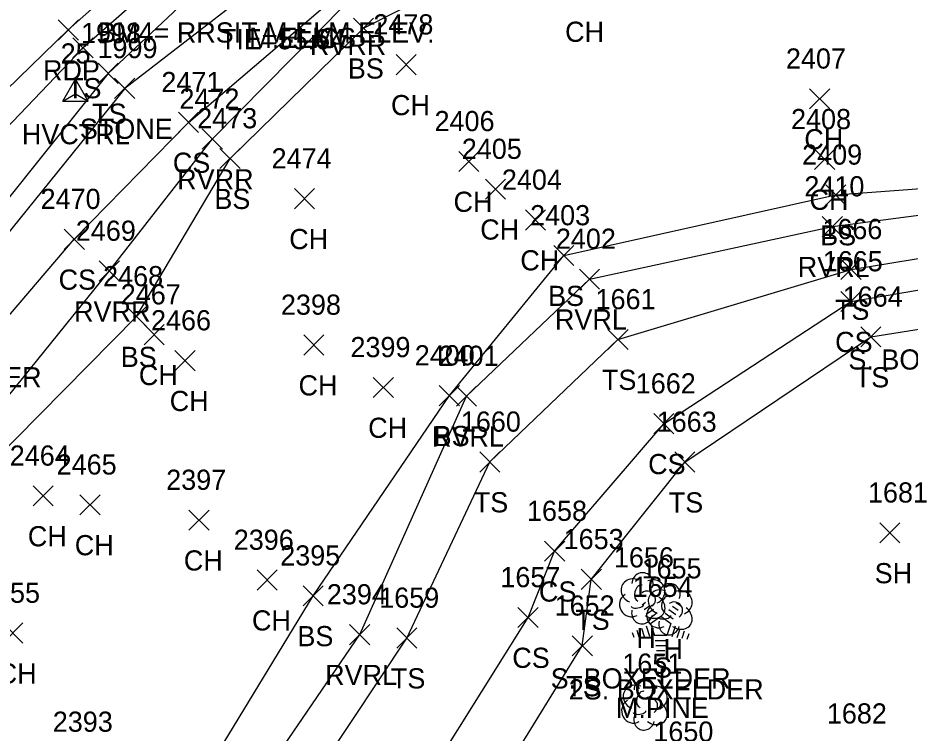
# Model space of a CAD drawing. Extents: x 1459992 to 1461532, y 647785 to 648535.
# Drawn here: x 1461337.5 to 1461426, y 648285.6 to 648356.5 of the extents above; entities that cross this region are included whole.
import ezdxf

# ---------------------------------------------------------------- set-up
doc = ezdxf.new("R2010")
doc.units = 0
for name, color, linetype in [('C_A', 7, 'Continuous'), ('C_C', 7, 'Continuous'), ('C_I', 7, 'Continuous'), ('CPSM', 7, 'Continuous'), ('L_A', 7, 'Continuous'), ('L_C', 7, 'Continuous'), ('L_I', 7, 'Continuous'), ('L_TIC', 7, 'Continuous'), ('LASF', 7, 'Continuous'), ('LAWE', 7, 'Continuous'), ('LELB', 7, 'Continuous'), ('LTC', 7, 'Continuous'), ('LTD', 7, 'Continuous'), ('P_A', 7, 'Continuous'), ('P_TIC', 7, 'Continuous'), ('PET', 7, 'Continuous')]:
    doc.layers.add(name, color=color, linetype=linetype)

msp = doc.modelspace()

# ---------------------------------------------------------------- linework, layer by layer
at = {"layer": 'CPSM'}
for p, q in [((1461341.956, 648348.262), (1461343.206, 648350.427)), ((1461344.456, 648348.262), (1461343.206, 648350.427)), ((1461343.206, 648348.983), (1461343.206, 648350.427)), ((1461341.956, 648348.262), (1461343.206, 648348.983)), ((1461343.206, 648348.983), (1461343.206, 648348.983)), ((1461343.206, 648348.983), (1461344.456, 648348.262)), ((1461341.956, 648348.262), (1461344.456, 648348.262))]:
    msp.add_line(p, q, dxfattribs=at)
at = {"layer": 'L_TIC'}
for points in [[(1461370.773, 648354.493), (1461372.773, 648356.493)], [(1461372.773, 648354.493), (1461370.773, 648356.493)], [(1461342.966, 648352.542), (1461344.966, 648354.542)], [(1461344.966, 648352.542), (1461342.966, 648354.542)], [(1461375.004, 648350.864), (1461377.004, 648352.864)], [(1461377.004, 648350.864), (1461375.004, 648352.864)], [(1461345.459, 648350.009), (1461347.459, 648352.009)], [(1461347.459, 648350.009), (1461345.459, 648352.009)], [(1461347.098, 648348.519), (1461349.098, 648350.519)], [(1461349.098, 648348.519), (1461347.098, 648350.519)], [(1461415.982, 648347.482), (1461417.982, 648349.482)], [(1461417.982, 648347.482), (1461415.982, 648349.482)], [(1461353.424, 648345.152), (1461355.424, 648347.152)], [(1461355.424, 648345.152), (1461353.424, 648347.152)], [(1461355.783, 648343.505), (1461357.783, 648345.505)], [(1461357.783, 648343.505), (1461355.783, 648345.505)], [(1461357.54, 648341.564), (1461359.54, 648343.564)], [(1461359.54, 648341.564), (1461357.54, 648343.564)], [(1461381.204, 648341.281), (1461383.204, 648343.281)], [(1461383.204, 648341.281), (1461381.204, 648343.281)], [(1461416.492, 648341.48), (1461418.492, 648343.48)], [(1461418.492, 648341.48), (1461416.492, 648343.48)], [(1461383.852, 648338.532), (1461385.852, 648340.532)], [(1461385.852, 648338.532), (1461383.852, 648340.532)], [(1461364.915, 648337.585), (1461366.915, 648339.585)], [(1461366.915, 648337.585), (1461364.915, 648339.585)], [(1461417.599, 648337.961), (1461419.599, 648339.961)], [(1461419.599, 648337.961), (1461417.599, 648339.961)], [(1461387.825, 648335.479), (1461389.825, 648337.479)], [(1461389.825, 648335.479), (1461387.825, 648337.479)], [(1461417.251, 648334.818), (1461419.251, 648336.818)], [(1461419.251, 648334.818), (1461417.251, 648336.818)], [(1461342.1, 648333.566), (1461344.1, 648335.566)], [(1461344.1, 648333.566), (1461342.1, 648335.566)], [(1461390.623, 648331.953), (1461392.623, 648333.953)], [(1461392.623, 648331.953), (1461390.623, 648333.953)], [(1461345.563, 648330.413), (1461347.563, 648332.413)], [(1461347.563, 648330.413), (1461345.563, 648332.413)], [(1461419.097, 648330.579), (1461421.097, 648332.579)], [(1461421.097, 648330.579), (1461419.097, 648332.579)], [(1461393.178, 648329.617), (1461395.178, 648331.617)], [(1461395.178, 648329.617), (1461393.178, 648331.617)], [(1461419.081, 648327.389), (1461421.081, 648329.389)], [(1461421.081, 648327.389), (1461419.081, 648329.389)], [(1461348.259, 648325.907), (1461350.259, 648327.907)], [(1461350.259, 648325.907), (1461348.259, 648327.907)], [(1461350.008, 648324.108), (1461352.008, 648326.108)], [(1461352.008, 648324.108), (1461350.008, 648326.108)], [(1461365.839, 648323.084), (1461367.839, 648325.084)], [(1461367.839, 648323.084), (1461365.839, 648325.084)], [(1461395.995, 648323.631), (1461397.995, 648325.631)], [(1461397.995, 648323.631), (1461395.995, 648325.631)], [(1461421.059, 648323.886), (1461423.059, 648325.886)], [(1461423.059, 648323.886), (1461421.059, 648325.886)], [(1461353.065, 648321.537), (1461355.065, 648323.537)], [(1461355.065, 648321.537), (1461353.065, 648323.537)], [(1461372.741, 648318.879), (1461374.741, 648320.879)], [(1461374.741, 648318.879), (1461372.741, 648320.879)], [(1461379.277, 648318.065), (1461381.277, 648320.065)], [(1461381.277, 648318.065), (1461379.277, 648320.065)], [(1461380.983, 648318.016), (1461382.983, 648320.016)], [(1461382.983, 648318.016), (1461380.983, 648320.016)], [(1461400.544, 648315.282), (1461402.544, 648317.282)], [(1461402.544, 648315.282), (1461400.544, 648317.282)], [(1461383.29, 648311.493), (1461385.29, 648313.493)], [(1461385.29, 648311.493), (1461383.29, 648313.493)], [(1461402.621, 648311.479), (1461404.621, 648313.479)], [(1461404.621, 648311.479), (1461402.621, 648313.479)], [(1461339.003, 648308.127), (1461341.003, 648310.127)], [(1461341.003, 648308.127), (1461339.003, 648310.127)], [(1461343.655, 648307.242), (1461345.655, 648309.242)], [(1461345.655, 648307.242), (1461343.655, 648309.242)], [(1461354.466, 648305.727), (1461356.466, 648307.727)], [(1461356.466, 648305.727), (1461354.466, 648307.727)], [(1461422.954, 648304.466), (1461424.954, 648306.466)], [(1461424.954, 648304.466), (1461422.954, 648306.466)], [(1461389.715, 648302.649), (1461391.715, 648304.649)], [(1461391.715, 648302.649), (1461389.715, 648304.649)], [(1461361.22, 648299.783), (1461363.22, 648301.783)], [(1461363.22, 648299.783), (1461361.22, 648301.783)], [(1461393.351, 648299.848), (1461395.351, 648301.848)], [(1461395.351, 648299.848), (1461393.351, 648301.848)], [(1461365.77, 648298.226), (1461367.77, 648300.226)], [(1461367.77, 648298.226), (1461365.77, 648300.226)], [(1461387.077, 648296.078), (1461389.077, 648298.078)], [(1461389.077, 648296.078), (1461387.077, 648298.078)], [(1461336.008, 648294.528), (1461338.008, 648296.528)], [(1461338.008, 648294.528), (1461336.008, 648296.528)], [(1461370.394, 648294.376), (1461372.394, 648296.376)], [(1461372.394, 648294.376), (1461370.394, 648296.376)], [(1461375.071, 648294.04), (1461377.071, 648296.04)], [(1461377.071, 648294.04), (1461375.071, 648296.04)], [(1461392.455, 648293.262), (1461394.455, 648295.262)], [(1461394.455, 648293.262), (1461392.455, 648295.262)]]:
    msp.add_lwpolyline(points, dxfattribs=at)
at = {"layer": 'LASF'}
msp.add_lwpolyline([(1461385.213, 648380.492), (1461366.248, 648363.55), (1461348.098, 648349.519), (1461330.912, 648328.279), (1461323.073, 648320.206), (1461313.493, 648297.123), (1461306.874, 648275.606), (1461301.288, 648261.14), (1461300.891, 648254.869), (1461298.603, 648250.96), (1461295.289, 648245.182), (1461300.607, 648235.351), (1461302.655, 648226.754), (1461299.855, 648225.177), (1461298.501, 648223.598), (1461297.241, 648222.361)], dxfattribs=at)
at = {"layer": 'LAWE'}
for points in [[(1461302.494, 648251.414), (1461304.732, 648255.86), (1461311.515, 648272.047), (1461318.184, 648292.347), (1461320.876, 648299.253), (1461325.88, 648305.325), (1461332.947, 648314.572), (1461346.563, 648331.413), (1461356.783, 648344.505), (1461369.936, 648357.821), (1461389.241, 648367.573), (1461411.269, 648373.546), (1461437.484, 648371.916), (1461454.448, 648377.931), (1461478.943, 648382.173)], [(1461220.159, 648021.615), (1461235.47, 648039.294), (1461252.966, 648048.327), (1461267.663, 648064.216), (1461276.22, 648071.524), (1461288.833, 648087.698), (1461307.75, 648107.551), (1461316.994, 648127.784), (1461326.453, 648138.792), (1461334.868, 648155.88), (1461340.573, 648163.303), (1461349.799, 648178.335), (1461354.706, 648199.541), (1461353.8, 648220.98), (1461352.341, 648246.452), (1461354.078, 648262.219), (1461358.254, 648276.136), (1461371.394, 648295.376), (1461381.983, 648319.016), (1461394.178, 648330.617), (1461418.251, 648335.818), (1461440.86, 648338.789), (1461464.612, 648337.5), (1461486.388, 648342.471)]]:
    msp.add_lwpolyline(points, dxfattribs=at)
at = {"layer": 'LELB'}
for points in [[(1461437.888, 648410.488), (1461418.935, 648407.67), (1461409.615, 648403.832), (1461397.123, 648398.784), (1461381.61, 648386.31), (1461361.675, 648369.148), (1461343.966, 648353.542), (1461325.103, 648333.829), (1461318.696, 648322.255), (1461308.654, 648307.17), (1461301.589, 648300.067), (1461298.1, 648291.151), (1461293.267, 648263.285), (1461293.552, 648252.72), (1461292.905, 648243.507), (1461295.985, 648233.828), (1461296.733, 648225.477), (1461296.732, 648222.487)], [(1461327.539, 648316.406), (1461343.1, 648334.566), (1461354.424, 648346.152), (1461368.865, 648358.513), (1461384.187, 648376.106), (1461404.449, 648390.112), (1461421.156, 648401.485), (1461440.471, 648405.654), (1461476.934, 648404.698)], [(1461409.615, 648403.832), (1461399.481, 648396.087), (1461384.513, 648382.595), (1461363.674, 648367.201), (1461346.459, 648351.009), (1461329.681, 648330.054), (1461321.263, 648319.556), (1461311.802, 648297.779), (1461304.882, 648276.195), (1461298.284, 648261.218), (1461298.603, 648250.96)], [(1461308.559, 648239.319), (1461311.248, 648242.529), (1461308.112, 648247.085), (1461308.77, 648252.863), (1461315.171, 648270.035), (1461321.583, 648291.019), (1461329.024, 648302.011), (1461334.847, 648312.35), (1461349.259, 648326.907), (1461358.54, 648342.564), (1461371.773, 648355.493), (1461390.676, 648365.061), (1461413.445, 648369.696), (1461437.721, 648367.905), (1461455.543, 648374.902), (1461479.25, 648378.908)], [(1461216.735, 648025.379), (1461232.531, 648043.682), (1461249.111, 648052.696), (1461265.41, 648068.573), (1461273.176, 648074.771), (1461285.769, 648090.042), (1461304.003, 648110.191), (1461314.102, 648129.874), (1461321.787, 648141.876), (1461329.36, 648157.887), (1461338.075, 648167.022), (1461343.94, 648182.363), (1461347.487, 648202.693), (1461348.844, 648222.98), (1461349.522, 648245.94), (1461349.946, 648262.877), (1461353.497, 648277.365), (1461366.77, 648299.226), (1461380.277, 648319.065), (1461391.623, 648332.953), (1461418.599, 648338.961), (1461441.306, 648340.652), (1461465.695, 648340.733), (1461485.923, 648346.235)], [(1461358.31, 648179.355), (1461357.653, 648195.692), (1461360.601, 648216.915), (1461360.157, 648235.422), (1461360.989, 648255.356), (1461365.028, 648278.404), (1461376.071, 648295.04), (1461384.29, 648312.493), (1461396.995, 648324.631), (1461420.097, 648331.579), (1461440.679, 648334.945), (1461465.222, 648335.03), (1461486.95, 648334.589)], [(1461357.653, 648195.692), (1461372.62, 648210.835), (1461379.226, 648235), (1461368.439, 648254.002), (1461374.317, 648275.061), (1461388.077, 648297.078), (1461390.715, 648303.649), (1461401.544, 648316.282), (1461420.081, 648328.389), (1461441.846, 648332.112), (1461465.283, 648329.963)], [(1461372.62, 648210.835), (1461395.441, 648232.259), (1461377.271, 648257.091), (1461379.775, 648272.055), (1461393.455, 648294.262), (1461394.351, 648300.848), (1461403.621, 648312.479), (1461422.059, 648324.886), (1461442.394, 648328.132), (1461465.283, 648329.963), (1461486.61, 648325.746)]]:
    msp.add_lwpolyline(points, dxfattribs=at)
at = {"layer": 'LTC'}
for p, q in [((1461399.379, 648298.32), (1461399.734, 648298.577)), ((1461402.778, 648298.56), (1461403.197, 648298.256)), ((1461399.589, 648297.855), (1461400.118, 648298.239)), ((1461399.799, 648297.389), (1461400.502, 648297.9)), ((1461402.036, 648297.864), (1461402.715, 648297.37)), ((1461402.407, 648298.212), (1461402.956, 648297.813)), ((1461400.008, 648296.923), (1461400.887, 648297.561)), ((1461400.233, 648296.468), (1461401.244, 648297.202)), ((1461401.244, 648297.202), (1461402.242, 648296.477)), ((1461401.664, 648297.515), (1461402.474, 648296.927)), ((1461399.323, 648296.032), (1461399.594, 648295.197)), ((1461399.778, 648296.249), (1461400.109, 648295.23)), ((1461400.233, 648296.468), (1461400.62, 648295.275)), ((1461402.242, 648296.477), (1461401.85, 648295.275)), ((1461402.679, 648296.207), (1461402.341, 648295.167)), ((1461403.124, 648295.956), (1461402.836, 648295.072)), ((1461398.412, 648295.599), (1461398.564, 648295.131)), ((1461398.867, 648295.816), (1461399.079, 648295.164)), ((1461401.85, 648295.275), (1461400.62, 648295.275)), ((1461403.568, 648295.706), (1461403.331, 648294.977)), ((1461404.012, 648295.456), (1461403.826, 648294.882)), ((1461401.812, 648294.775), (1461400.667, 648294.775)), ((1461401.728, 648294.275), (1461400.74, 648294.275)), ((1461401.644, 648293.775), (1461400.813, 648293.775)), ((1461401.561, 648293.275), (1461400.886, 648293.275))]:
    msp.add_line(p, q, dxfattribs=at)
at = {"layer": 'LTD'}
for p, q in [((1461399.386, 648299.034), (1461399.386, 648299.034)), ((1461399.386, 648299.034), (1461399.386, 648299.034)), ((1461402.076, 648297.947), (1461402.076, 648297.947)), ((1461402.076, 648297.947), (1461402.076, 648297.947)), ((1461399.597, 648288.5), (1461399.597, 648288.5)), ((1461399.597, 648288.5), (1461399.597, 648288.5))]:
    msp.add_line(p, q, dxfattribs=at)
for centre in [(1461399.432, 648300.468), (1461402.123, 648299.381), (1461399.644, 648289.934)]:
    msp.add_arc(centre, 1.047, 335.52715, 180.95627, dxfattribs=at)
for centre, major_axis, ratio, start_param, end_param in [((1461398.594, 648299.7), (1.21, -0.512), 0.895232, 1.570796, 4.712389), ((1461399.177, 648299.492), (-0.208, -0.792), 0.645439, 3.141593, 6.283185), ((1461400.427, 648299.617), (-1.141, -0.483), 0.949671, 1.570796, 4.712389), ((1461399.886, 648298.867), (-0.5, 0.667), 0.989748, 3.141593, 6.283185), ((1461401.284, 648298.614), (1.21, -0.512), 0.895232, 1.570796, 4.712389), ((1461403.118, 648298.531), (-1.141, -0.483), 0.949671, 1.570796, 4.712389), ((1461398.302, 648298.325), (0.584, -1.042), 0.959034, 3.141593, 6.283185), ((1461400.386, 648298.201), (-1.09, 0.792), 0.841452, 1.570796, 4.712389), ((1461401.868, 648298.406), (-0.208, -0.792), 0.645439, 3.141593, 6.283185), ((1461402.576, 648297.781), (-0.5, 0.667), 0.989748, 3.141593, 6.283185), ((1461399.386, 648297.534), (0.265, 1.061), 0.942809, 1.570796, 4.712389), ((1461398.927, 648298.284), (-0.625, -0.083), 0.423636, 0, 3.141593), ((1461400.993, 648297.239), (0.584, -1.042), 0.959034, 3.141593, 6.283185), ((1461403.076, 648297.114), (-1.09, 0.792), 0.841452, 1.570796, 4.712389), ((1461401.618, 648297.197), (-0.625, -0.083), 0.423636, 0, 3.141593), ((1461402.076, 648296.447), (0.265, 1.061), 0.942809, 1.570796, 4.712389), ((1461398.806, 648289.167), (1.21, -0.512), 0.895232, 1.570796, 4.712389), ((1461399.389, 648288.959), (-0.208, -0.792), 0.645439, 3.141593, 6.283185), ((1461400.639, 648289.084), (-1.141, -0.483), 0.949671, 1.570796, 4.712389), ((1461398.514, 648287.792), (0.584, -1.042), 0.959034, 3.141593, 6.283185), ((1461400.097, 648288.334), (-0.5, 0.667), 0.989748, 3.141593, 6.283185), ((1461400.597, 648287.667), (-1.09, 0.792), 0.841452, 1.570796, 4.712389), ((1461399.598, 648287), (0.265, 1.061), 0.942809, 1.570796, 4.712389), ((1461399.139, 648287.75), (-0.625, -0.083), 0.423636, 0, 3.141593)]:
    msp.add_ellipse(centre, major_axis=major_axis, ratio=ratio, start_param=start_param, end_param=end_param, dxfattribs=at)
at = {"layer": 'P_TIC'}
for points in [[(1461341.503, 648354.317), (1461343.503, 648356.317)], [(1461343.503, 648354.317), (1461341.503, 648356.317)]]:
    msp.add_lwpolyline(points, dxfattribs=at)
at = {"layer": 'PET'}
msp.add_lwpolyline([(1461431.711, 648423.556), (1461406.606, 648408.469), (1461395.323, 648400.735), (1461379.715, 648387.972), (1461359.995, 648370.892), (1461342.503, 648355.317), (1461322.757, 648336.157), (1461306.541, 648318.18), (1461292.231, 648305.652), (1461275.705, 648293.856), (1461255.229, 648282.826), (1461238.596, 648275.701), (1461226.2, 648272.493), (1461213.087, 648269.852), (1461197.04, 648267.634), (1461176.943, 648267.356), (1461164.213, 648269.583)], dxfattribs=at)

# ---------------------------------------------------------------- texts
at = {"layer": 'C_A'}
msp.add_text('HVCTRL', height=2, dxfattribs=at).set_placement((1461337.899, 648343.983))
at = {"layer": 'C_C'}
for s, p in [('BM4= RRSIT M.ELM ELEV:', (1461345.453, 648354.064)), ('TIE=55.64', (1461357.529, 648353.396))]:
    msp.add_text(s, height=2, dxfattribs=at).set_placement(p)
at = {"layer": 'C_I'}
msp.add_text('25', height=2, dxfattribs=at).set_placement((1461341.741, 648351.983))
at = {"layer": 'L_A'}
for s, p in [('CH', (1461391.752, 648354.135)), ('CS', (1461367.306, 648353.513)), ('RVRR', (1461366.448, 648352.821)), ('BS', (1461370.214, 648350.493)), ('TS', (1461342.375, 648348.542)), ('CH', (1461374.492, 648346.864)), ('TS', (1461344.868, 648346.009)), ('STONE', (1461343.642, 648344.519)), ('CH', (1461415.47, 648343.482)), ('CS', (1461352.865, 648341.152)), ('RVRR', (1461353.294, 648339.505)), ('BS', (1461356.98, 648337.564)), ('CH', (1461380.692, 648337.281)), ('CH', (1461415.98, 648337.48)), ('CH', (1461383.34, 648334.532)), ('BS', (1461417.04, 648333.961)), ('CH', (1461364.403, 648333.585)), ('CH', (1461387.313, 648331.479)), ('RVRL', (1461414.818, 648330.818)), ('CS', (1461341.541, 648329.566)), ('BS', (1461390.064, 648327.953)), ('TS', (1461418.506, 648326.579)), ('RVRR', (1461343.075, 648326.413)), ('RVRL', (1461390.745, 648325.617)), ('CS', (1461418.522, 648323.389)), ('BS', (1461347.7, 648321.907)), ('CH', (1461349.496, 648320.108)), ('TS', (1461395.404, 648319.631)), ('TS', (1461420.468, 648319.886)), ('CH', (1461365.328, 648319.084)), ('CH', (1461352.554, 648317.537)), ('CH', (1461372.229, 648314.879)), ('RVRL', (1461378.55, 648314.016)), ('BS', (1461378.718, 648314.065)), ('CS', (1461399.985, 648311.282)), ('TS', (1461382.699, 648307.493)), ('TS', (1461402.031, 648307.479)), ('CH', (1461338.491, 648304.127)), ('CH', (1461343.143, 648303.242)), ('CH', (1461353.954, 648301.727)), ('SH', (1461422.442, 648300.466)), ('CS', (1461389.156, 648298.649)), ('CH', (1461360.709, 648295.783)), ('TS', (1461392.76, 648295.848)), ('BS', (1461365.211, 648294.226)), ('H', (1461398.819, 648294.034)), ('CS', (1461386.518, 648292.078)), ('H', (1461401.509, 648292.947)), ('CH', (1461335.496, 648290.528)), ('RVRL', (1461367.961, 648290.376)), ('S', (1461400.57, 648291.112)), ('TS', (1461374.481, 648290.04)), ('TS', (1461391.865, 648289.262))]:
    msp.add_text(s, height=2, dxfattribs=at).set_placement(p)
at = {"layer": 'L_C'}
for s, p in [('M.ELM', (1461360.444, 648353.526)), ('S. BOXELDER', (1461419.837, 648321.648)), ('S.BOXELDER', (1461322.759, 648319.888)), ('S. BOXELDER', (1461390.323, 648290.034)), ('2S. BOXELDER', (1461392.116, 648288.947)), ('M.PINE', (1461396.791, 648287.112))]:
    msp.add_text(s, height=2, dxfattribs=at).set_placement(p)
at = {"layer": 'L_I'}
for s, p in [('1998', (1461343.766, 648354.009)), ('2478', (1461372.744, 648354.864)), ('1999', (1461345.398, 648352.519)), ('2407', (1461413.644, 648351.482)), ('2471', (1461351.731, 648349.152)), ('2472', (1461353.523, 648347.505)), ('2473', (1461355.28, 648345.564)), ('2406', (1461378.81, 648345.281)), ('2408', (1461414.153, 648345.48)), ('2405', (1461381.513, 648342.532)), ('2409', (1461415.253, 648341.961)), ('2474', (1461362.655, 648341.585)), ('2404', (1461385.486, 648339.479)), ('2410', (1461415.472, 648338.818)), ('2470', (1461339.753, 648337.566)), ('2403', (1461388.284, 648335.953)), ('1666', (1461417.254, 648334.579)), ('2469', (1461343.248, 648334.413)), ('2402', (1461390.839, 648333.617)), ('1665', (1461417.293, 648331.389)), ('2468', (1461345.952, 648329.907)), ('2467', (1461347.701, 648328.108)), ('1661', (1461394.774, 648327.631)), ('1664', (1461419.271, 648327.886)), ('2398', (1461363.58, 648327.084)), ('2466', (1461350.703, 648325.537)), ('2399', (1461370.473, 648322.879)), ('2400', (1461376.852, 648322.065)), ('2401', (1461379.212, 648322.016)), ('1662', (1461398.757, 648319.282)), ('1660', (1461381.416, 648315.493)), ('1663', (1461400.834, 648315.479)), ('2464', (1461336.696, 648312.127)), ('2465', (1461341.348, 648311.242)), ('2397', (1461352.206, 648309.727)), ('1681', (1461421.781, 648308.466)), ('1658', (1461387.975, 648306.649)), ('2396', (1461358.905, 648303.783)), ('1653', (1461391.61, 648303.848)), ('2395', (1461363.51, 648302.226)), ('1656', (1461396.59, 648302.034)), ('1655', (1461399.336, 648300.947)), ('1657', (1461385.337, 648300.078)), ('2455', (1461333.748, 648298.528)), ('2394', (1461368.134, 648298.376)), ('1654', (1461398.444, 648299.112)), ('1659', (1461373.323, 648298.04)), ('1652', (1461390.715, 648297.262)), ('1651', (1461397.424, 648291.5)), ('1682', (1461417.701, 648286.561)), ('2393', (1461340.963, 648285.746)), ('1650', (1461400.503, 648284.764))]:
    msp.add_text(s, height=2, dxfattribs=at).set_placement(p)
at = {"layer": 'LTC'}
msp.add_text('.', height=1.037, rotation=270, dxfattribs=at).set_placement((1461401.127, 648296.216))
at = {"layer": 'P_A'}
msp.add_text('RDP', height=2, dxfattribs=at).set_placement((1461339.991, 648350.317))

doc.saveas('drawing.dxf')
